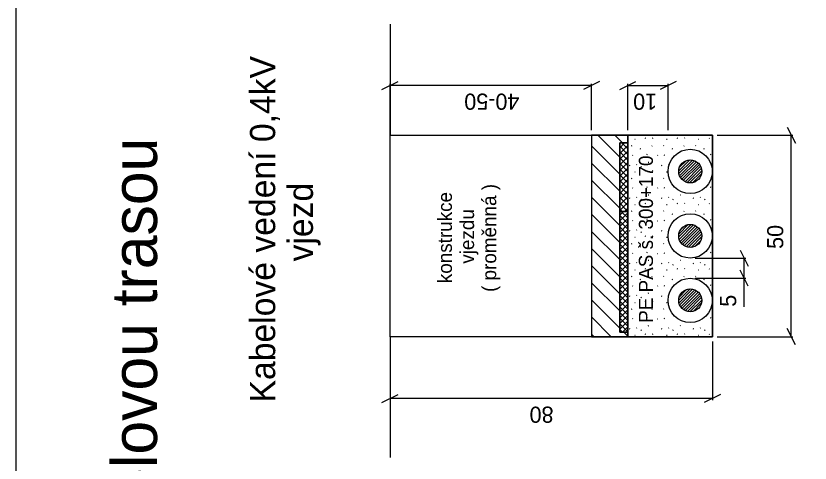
# Model space of a CAD drawing. Extents: x -762592 to -762444, y -1032635 to -1032425.
# Drawn here: x -762592.03 to -762560.49, y -1032598.54 to -1032580.78 of the extents above; entities that cross this region are included whole.
import ezdxf

# ---------------------------------------------------------------- set-up
doc = ezdxf.new("R2010")
doc.units = 0
for name, color, linetype in [('Chráničky - koruflex', 7, 'Continuous'), ('Implicitní', 7, 'Continuous'), ('Kabeláž - kabelové vedení HDV - stávající', 7, 'Continuous'), ('Tisk', 7, 'Continuous'), ('X ŘEZY TRASOU', 7, 'Continuous'), ('X ŘEZY TRASOU - KÓTY', 7, 'Continuous'), ('X ŘEZY TRASOU - ŠRAFY', 7, 'Continuous')]:
    doc.layers.add(name, color=color, linetype=linetype)

msp = doc.modelspace()

# ---------------------------------------------------------------- linework, layer by layer
at = {"layer": 'Kabeláž - kabelové vedení HDV - stávající'}
for p, q in [((-762565.703, -1032586.936), (-762565.271, -1032586.504)), ((-762565.696, -1032587.042), (-762565.164, -1032586.51)), ((-762565.674, -1032586.794), (-762565.414, -1032586.534)), ((-762565.67, -1032587.13), (-762565.077, -1032586.537)), ((-762565.632, -1032587.204), (-762565.002, -1032586.575)), ((-762565.582, -1032587.268), (-762564.939, -1032586.625)), ((-762565.523, -1032587.322), (-762564.885, -1032586.684)), ((-762565.453, -1032587.365), (-762564.842, -1032586.754)), ((-762565.371, -1032587.397), (-762564.81, -1032586.836)), ((-762565.275, -1032587.413), (-762564.793, -1032586.932)), ((-762565.152, -1032587.403), (-762564.803, -1032587.054)), ((-762565.702, -1032589.559), (-762565.207, -1032589.065)), ((-762565.697, -1032589.442), (-762565.325, -1032589.07)), ((-762565.683, -1032589.654), (-762565.113, -1032589.084)), ((-762565.65, -1032589.734), (-762565.033, -1032589.117)), ((-762565.614, -1032589.245), (-762565.524, -1032589.155)), ((-762565.605, -1032589.802), (-762564.965, -1032589.162)), ((-762565.55, -1032589.86), (-762564.907, -1032589.217)), ((-762565.484, -1032589.908), (-762564.859, -1032589.283)), ((-762565.409, -1032589.945), (-762564.822, -1032589.359)), ((-762565.318, -1032589.968), (-762564.799, -1032589.448)), ((-762565.209, -1032589.972), (-762564.795, -1032589.557)), ((-762565.055, -1032589.931), (-762564.837, -1032589.713)), ((-762565.704, -1032592.07), (-762565.257, -1032591.623)), ((-762565.694, -1032592.173), (-762565.153, -1032591.633)), ((-762565.68, -1032591.933), (-762565.394, -1032591.647)), ((-762565.667, -1032592.259), (-762565.068, -1032591.661)), ((-762565.626, -1032592.332), (-762564.994, -1032591.7)), ((-762565.576, -1032592.395), (-762564.932, -1032591.751)), ((-762565.516, -1032592.448), (-762564.88, -1032591.812)), ((-762565.444, -1032592.489), (-762564.837, -1032591.882)), ((-762565.361, -1032592.52), (-762564.808, -1032591.966)), ((-762565.262, -1032592.533), (-762564.794, -1032592.065)), ((-762565.134, -1032592.519), (-762564.808, -1032592.193))]:
    msp.add_line(p, q, dxfattribs=at)
at = {"layer": 'Tisk'}
msp.add_lwpolyline([(-762589.528, -1032529.685), (-762592.028, -1032529.685), (-762592.028, -1032634.685), (-762443.528, -1032634.685), (-762443.528, -1032529.685), (-762446.028, -1032529.685)], dxfattribs=at)
at = {"layer": 'X ŘEZY TRASOU'}
for p, q in [((-762577.169, -1032581.118), (-762577.169, -1032585.518)), ((-762577.169, -1032593.518), (-762577.169, -1032585.518)), ((-762577.169, -1032585.518), (-762567.729, -1032585.518)), ((-762569.169, -1032585.518), (-762569.169, -1032593.518)), ((-762567.729, -1032585.518), (-762567.729, -1032593.518)), ((-762567.729, -1032593.518), (-762567.729, -1032585.518)), ((-762567.729, -1032585.518), (-762564.369, -1032585.518)), ((-762564.369, -1032585.518), (-762564.369, -1032593.518)), ((-762568.049, -1032586.019), (-762567.853, -1032585.823)), ((-762567.729, -1032585.823), (-762568.049, -1032585.823)), ((-762568.049, -1032585.823), (-762568.049, -1032588.543)), ((-762567.729, -1032585.823), (-762568.049, -1032585.823)), ((-762568.049, -1032585.823), (-762568.049, -1032588.543)), ((-762568.049, -1032586.245), (-762567.729, -1032585.925)), ((-762567.729, -1032586.281), (-762568.049, -1032585.961)), ((-762567.729, -1032586.055), (-762567.96, -1032585.823)), ((-762567.729, -1032585.828), (-762567.734, -1032585.823)), ((-762567.729, -1032588.543), (-762567.729, -1032585.823)), ((-762567.729, -1032588.543), (-762567.729, -1032585.823)), ((-762568.049, -1032586.471), (-762567.729, -1032586.151)), ((-762567.729, -1032586.507), (-762568.049, -1032586.187)), ((-762568.049, -1032586.697), (-762567.729, -1032586.377)), ((-762567.729, -1032586.733), (-762568.049, -1032586.413)), ((-762568.049, -1032586.924), (-762567.729, -1032586.604)), ((-762567.729, -1032586.96), (-762568.049, -1032586.64)), ((-762568.049, -1032587.15), (-762567.729, -1032586.83)), ((-762567.729, -1032587.186), (-762568.049, -1032586.866)), ((-762568.049, -1032587.376), (-762567.729, -1032587.056)), ((-762567.729, -1032587.412), (-762568.049, -1032587.092)), ((-762568.049, -1032587.603), (-762567.729, -1032587.283)), ((-762567.729, -1032587.638), (-762568.049, -1032587.318)), ((-762568.049, -1032587.829), (-762567.729, -1032587.509)), ((-762567.729, -1032587.865), (-762568.049, -1032587.545)), ((-762568.049, -1032588.055), (-762567.729, -1032587.735)), ((-762567.729, -1032588.091), (-762568.049, -1032587.771)), ((-762568.049, -1032588.281), (-762567.729, -1032587.961)), ((-762567.729, -1032588.317), (-762568.049, -1032587.997)), ((-762568.049, -1032588.508), (-762567.729, -1032588.188)), ((-762567.729, -1032588.543), (-762568.049, -1032588.224)), ((-762567.955, -1032588.543), (-762568.049, -1032588.45)), ((-762568.049, -1032588.697), (-762567.895, -1032588.543)), ((-762568.049, -1032588.543), (-762567.729, -1032588.543)), ((-762568.049, -1032588.543), (-762567.729, -1032588.543)), ((-762568.049, -1032593.343), (-762568.049, -1032588.543)), ((-762568.049, -1032588.543), (-762567.729, -1032588.543)), ((-762567.729, -1032588.543), (-762568.049, -1032588.543)), ((-762568.049, -1032588.543), (-762568.049, -1032593.343)), ((-762567.729, -1032588.804), (-762567.989, -1032588.543)), ((-762567.858, -1032588.543), (-762567.729, -1032588.414)), ((-762567.729, -1032588.578), (-762567.763, -1032588.543)), ((-762567.729, -1032588.543), (-762567.729, -1032593.343)), ((-762567.729, -1032593.343), (-762567.729, -1032588.543)), ((-762568.049, -1032588.923), (-762567.729, -1032588.603)), ((-762567.729, -1032589.03), (-762568.049, -1032588.71)), ((-762568.049, -1032589.149), (-762567.729, -1032588.829)), ((-762567.729, -1032589.256), (-762568.049, -1032588.936)), ((-762568.049, -1032589.376), (-762567.729, -1032589.056)), ((-762567.729, -1032589.483), (-762568.049, -1032589.163)), ((-762568.049, -1032589.602), (-762567.729, -1032589.282)), ((-762567.729, -1032589.709), (-762568.049, -1032589.389)), ((-762568.049, -1032589.828), (-762567.729, -1032589.508)), ((-762567.729, -1032589.935), (-762568.049, -1032589.615)), ((-762568.049, -1032590.054), (-762567.729, -1032589.734)), ((-762567.729, -1032590.162), (-762568.049, -1032589.842)), ((-762568.049, -1032590.281), (-762567.729, -1032589.961)), ((-762567.729, -1032590.388), (-762568.049, -1032590.068)), ((-762568.049, -1032590.507), (-762567.729, -1032590.187)), ((-762567.729, -1032590.614), (-762568.049, -1032590.294)), ((-762568.049, -1032590.733), (-762567.729, -1032590.413)), ((-762567.729, -1032590.84), (-762568.049, -1032590.52)), ((-762568.049, -1032590.959), (-762567.729, -1032590.639)), ((-762567.729, -1032591.067), (-762568.049, -1032590.747)), ((-762568.049, -1032591.186), (-762567.729, -1032590.866)), ((-762567.729, -1032591.293), (-762568.049, -1032590.973)), ((-762568.049, -1032591.412), (-762567.729, -1032591.092)), ((-762567.729, -1032591.519), (-762568.049, -1032591.199)), ((-762568.049, -1032591.638), (-762567.729, -1032591.318)), ((-762567.729, -1032591.745), (-762568.049, -1032591.425)), ((-762568.049, -1032591.865), (-762567.729, -1032591.545)), ((-762567.729, -1032591.972), (-762568.049, -1032591.652)), ((-762568.049, -1032592.091), (-762567.729, -1032591.771)), ((-762567.729, -1032592.198), (-762568.049, -1032591.878)), ((-762568.049, -1032592.317), (-762567.729, -1032591.997)), ((-762567.729, -1032592.424), (-762568.049, -1032592.104)), ((-762568.049, -1032592.543), (-762567.729, -1032592.223)), ((-762567.729, -1032592.651), (-762568.049, -1032592.331)), ((-762568.049, -1032592.77), (-762567.729, -1032592.45)), ((-762567.729, -1032592.877), (-762568.049, -1032592.557)), ((-762568.049, -1032592.996), (-762567.729, -1032592.676)), ((-762567.729, -1032593.103), (-762568.049, -1032592.783)), ((-762568.049, -1032593.222), (-762567.729, -1032592.902)), ((-762567.729, -1032593.329), (-762568.049, -1032593.009)), ((-762567.941, -1032593.343), (-762568.049, -1032593.236)), ((-762567.944, -1032593.343), (-762567.729, -1032593.128)), ((-762577.169, -1032593.518), (-762577.169, -1032598.318)), ((-762567.729, -1032593.518), (-762577.169, -1032593.518)), ((-762567.729, -1032593.343), (-762568.049, -1032593.343)), ((-762568.049, -1032593.343), (-762567.729, -1032593.343)), ((-762564.369, -1032593.518), (-762567.729, -1032593.518)), ((-762577.169, -1032595.118), (-762577.169, -1032597.413))]:
    msp.add_line(p, q, dxfattribs=at)
for centre, radius in [((-762565.249, -1032586.958), 0.88), ((-762565.249, -1032586.958), 0.456), ((-762565.249, -1032589.518), 0.88), ((-762565.249, -1032589.518), 0.456), ((-762565.249, -1032592.078), 0.88), ((-762565.249, -1032592.078), 0.456)]:
    msp.add_circle(centre, radius, dxfattribs=at)
at = {"layer": 'X ŘEZY TRASOU - KÓTY'}
for p, q in [((-762577.489, -1032583.709), (-762576.849, -1032583.389)), ((-762577.169, -1032585.518), (-762577.169, -1032583.485)), ((-762568.849, -1032583.389), (-762569.489, -1032583.709)), ((-762569.169, -1032585.326), (-762569.169, -1032583.485)), ((-762568.049, -1032583.709), (-762567.409, -1032583.389)), ((-762567.729, -1032585.326), (-762567.729, -1032583.485)), ((-762565.809, -1032583.389), (-762566.449, -1032583.709)), ((-762566.129, -1032585.326), (-762566.129, -1032583.485)), ((-762569.169, -1032583.549), (-762577.169, -1032583.549)), ((-762567.729, -1032583.549), (-762566.129, -1032583.549)), ((-762561.394, -1032585.198), (-762561.074, -1032585.838)), ((-762564.177, -1032585.518), (-762561.17, -1032585.518)), ((-762561.234, -1032593.518), (-762561.234, -1032585.518)), ((-762563.264, -1032590.078), (-762562.944, -1032590.718)), ((-762565.057, -1032590.398), (-762563.04, -1032590.398)), ((-762563.104, -1032591.198), (-762563.104, -1032590.398)), ((-762562.944, -1032591.518), (-762563.264, -1032590.878)), ((-762565.057, -1032591.198), (-762563.04, -1032591.198)), ((-762563.104, -1032592.331), (-762563.104, -1032591.198)), ((-762561.074, -1032593.838), (-762561.394, -1032593.198)), ((-762564.177, -1032593.518), (-762561.17, -1032593.518)), ((-762577.169, -1032593.71), (-762577.169, -1032596.039)), ((-762564.369, -1032593.71), (-762564.369, -1032596.039)), ((-762577.489, -1032596.135), (-762576.849, -1032595.815)), ((-762564.369, -1032595.975), (-762577.169, -1032595.975)), ((-762564.049, -1032595.815), (-762564.689, -1032596.135))]:
    msp.add_line(p, q, dxfattribs=at)
at = {"layer": 'X ŘEZY TRASOU - ŠRAFY'}
for p, q in [((-762569.169, -1032585.518), (-762569.169, -1032593.518)), ((-762567.729, -1032585.518), (-762569.169, -1032585.518)), ((-762568.049, -1032586.387), (-762568.917, -1032585.518)), ((-762567.933, -1032585.823), (-762568.238, -1032585.518)), ((-762567.729, -1032585.823), (-762567.729, -1032585.518)), ((-762564.369, -1032585.518), (-762567.729, -1032585.518)), ((-762567.729, -1032585.518), (-762567.729, -1032585.823)), ((-762567.454, -1032585.677), (-762567.43, -1032585.674)), ((-762567.007, -1032585.652), (-762567.032, -1032585.641)), ((-762566.743, -1032585.635), (-762566.726, -1032585.624)), ((-762566.19, -1032585.677), (-762566.165, -1032585.674)), ((-762565.743, -1032585.652), (-762565.767, -1032585.641)), ((-762565.478, -1032585.635), (-762565.462, -1032585.624)), ((-762564.925, -1032585.677), (-762564.901, -1032585.674)), ((-762564.478, -1032585.652), (-762564.503, -1032585.641)), ((-762564.369, -1032586.958), (-762564.369, -1032585.518)), ((-762568.049, -1032587.065), (-762569.169, -1032585.945)), ((-762568.049, -1032588.543), (-762568.049, -1032585.823)), ((-762568.049, -1032585.823), (-762567.729, -1032585.823)), ((-762567.729, -1032585.823), (-762567.729, -1032588.543)), ((-762567.575, -1032585.945), (-762567.558, -1032585.934)), ((-762566.772, -1032585.955), (-762566.756, -1032585.944)), ((-762566.31, -1032585.945), (-762566.294, -1032585.934)), ((-762565.507, -1032585.955), (-762565.491, -1032585.944)), ((-762565.046, -1032585.945), (-762565.029, -1032585.934)), ((-762567.522, -1032586.321), (-762567.547, -1032586.31)), ((-762567.208, -1032586.074), (-762567.233, -1032586.063)), ((-762566.945, -1032586.294), (-762566.969, -1032586.283)), ((-762566.55, -1032586.329), (-762566.534, -1032586.319)), ((-762566.258, -1032586.321), (-762566.282, -1032586.31)), ((-762565.944, -1032586.074), (-762565.968, -1032586.063)), ((-762564.679, -1032586.074), (-762564.703, -1032586.063)), ((-762564.416, -1032586.294), (-762564.44, -1032586.283)), ((-762568.049, -1032587.744), (-762569.169, -1032586.624)), ((-762566.913, -1032586.596), (-762566.897, -1032586.586)), ((-762564.384, -1032586.596), (-762564.369, -1032586.586)), ((-762564.369, -1032586.586), (-762564.368, -1032586.586)), ((-762567.633, -1032586.732), (-762567.657, -1032586.721)), ((-762567.454, -1032586.974), (-762567.43, -1032586.971)), ((-762567.382, -1032586.693), (-762567.366, -1032586.682)), ((-762567.208, -1032586.789), (-762567.192, -1032586.778)), ((-762567.202, -1032586.778), (-762567.186, -1032586.767)), ((-762567.007, -1032586.949), (-762567.032, -1032586.938)), ((-762566.743, -1032586.932), (-762566.726, -1032586.921)), ((-762566.369, -1032586.732), (-762566.393, -1032586.721)), ((-762566.19, -1032586.974), (-762566.165, -1032586.971)), ((-762566.118, -1032586.693), (-762566.102, -1032586.682)), ((-762564.369, -1032589.518), (-762564.369, -1032586.958)), ((-762567.575, -1032587.242), (-762567.558, -1032587.231)), ((-762566.772, -1032587.252), (-762566.756, -1032587.241)), ((-762566.31, -1032587.242), (-762566.294, -1032587.231)), ((-762568.049, -1032588.423), (-762569.169, -1032587.303)), ((-762567.208, -1032587.371), (-762567.233, -1032587.36)), ((-762566.945, -1032587.59), (-762566.969, -1032587.58)), ((-762564.416, -1032587.59), (-762564.44, -1032587.58)), ((-762567.522, -1032587.618), (-762567.547, -1032587.607)), ((-762566.913, -1032587.893), (-762566.897, -1032587.883)), ((-762566.55, -1032587.626), (-762566.534, -1032587.616)), ((-762566.258, -1032587.618), (-762566.282, -1032587.607)), ((-762565.649, -1032587.893), (-762565.633, -1032587.883)), ((-762564.384, -1032587.893), (-762564.369, -1032587.883)), ((-762564.369, -1032587.883), (-762564.368, -1032587.883)), ((-762568.049, -1032589.102), (-762569.169, -1032587.982)), ((-762567.633, -1032588.029), (-762567.657, -1032588.018)), ((-762567.382, -1032587.99), (-762567.366, -1032587.979)), ((-762567.208, -1032588.086), (-762567.192, -1032588.075)), ((-762567.202, -1032588.075), (-762567.186, -1032588.064)), ((-762566.743, -1032588.229), (-762566.726, -1032588.218)), ((-762566.369, -1032588.029), (-762566.393, -1032588.018)), ((-762566.118, -1032587.99), (-762566.102, -1032587.979)), ((-762565.943, -1032588.086), (-762565.927, -1032588.075)), ((-762565.937, -1032588.075), (-762565.921, -1032588.064)), ((-762565.478, -1032588.229), (-762565.462, -1032588.218)), ((-762565.104, -1032588.029), (-762565.128, -1032588.018)), ((-762564.853, -1032587.99), (-762564.837, -1032587.979)), ((-762564.679, -1032588.086), (-762564.663, -1032588.075)), ((-762564.673, -1032588.075), (-762564.656, -1032588.064)), ((-762568.049, -1032593.343), (-762568.049, -1032588.543)), ((-762567.729, -1032588.543), (-762567.729, -1032593.343)), ((-762567.575, -1032588.539), (-762567.558, -1032588.528)), ((-762567.454, -1032588.271), (-762567.43, -1032588.268)), ((-762567.007, -1032588.246), (-762567.032, -1032588.235)), ((-762566.772, -1032588.549), (-762566.756, -1032588.538)), ((-762566.31, -1032588.539), (-762566.294, -1032588.528)), ((-762566.19, -1032588.271), (-762566.165, -1032588.268)), ((-762565.743, -1032588.246), (-762565.767, -1032588.235)), ((-762565.507, -1032588.549), (-762565.491, -1032588.538)), ((-762565.046, -1032588.539), (-762565.029, -1032588.528)), ((-762564.925, -1032588.271), (-762564.901, -1032588.268)), ((-762564.478, -1032588.246), (-762564.503, -1032588.235)), ((-762568.049, -1032589.781), (-762569.169, -1032588.661)), ((-762567.208, -1032588.668), (-762567.233, -1032588.657)), ((-762565.944, -1032588.668), (-762565.968, -1032588.657)), ((-762564.679, -1032588.668), (-762564.703, -1032588.657)), ((-762567.522, -1032588.914), (-762567.547, -1032588.904)), ((-762566.945, -1032588.887), (-762566.969, -1032588.877)), ((-762566.913, -1032589.19), (-762566.897, -1032589.18)), ((-762566.55, -1032588.923), (-762566.534, -1032588.913)), ((-762566.258, -1032588.914), (-762566.282, -1032588.904)), ((-762564.416, -1032588.887), (-762564.44, -1032588.877)), ((-762564.384, -1032589.19), (-762564.369, -1032589.18)), ((-762564.369, -1032589.18), (-762564.368, -1032589.18)), ((-762568.049, -1032590.459), (-762569.169, -1032589.339)), ((-762567.633, -1032589.326), (-762567.657, -1032589.315)), ((-762567.382, -1032589.287), (-762567.366, -1032589.276)), ((-762567.208, -1032589.383), (-762567.192, -1032589.372)), ((-762567.202, -1032589.372), (-762567.186, -1032589.361)), ((-762566.369, -1032589.326), (-762566.393, -1032589.315)), ((-762566.118, -1032589.287), (-762566.102, -1032589.276)), ((-762567.454, -1032589.568), (-762567.43, -1032589.565)), ((-762567.007, -1032589.543), (-762567.032, -1032589.532)), ((-762566.743, -1032589.526), (-762566.726, -1032589.515)), ((-762566.19, -1032589.568), (-762566.165, -1032589.565)), ((-762564.369, -1032592.078), (-762564.369, -1032589.518)), ((-762568.049, -1032591.138), (-762569.169, -1032590.018)), ((-762567.575, -1032589.836), (-762567.558, -1032589.825)), ((-762567.208, -1032589.965), (-762567.233, -1032589.954)), ((-762566.772, -1032589.846), (-762566.756, -1032589.835)), ((-762566.31, -1032589.836), (-762566.294, -1032589.825)), ((-762567.522, -1032590.211), (-762567.547, -1032590.201)), ((-762566.945, -1032590.184), (-762566.969, -1032590.174)), ((-762566.55, -1032590.22), (-762566.534, -1032590.21)), ((-762566.258, -1032590.211), (-762566.282, -1032590.201)), ((-762564.416, -1032590.184), (-762564.44, -1032590.174)), ((-762568.049, -1032591.817), (-762569.169, -1032590.697)), ((-762567.633, -1032590.623), (-762567.657, -1032590.612)), ((-762567.382, -1032590.583), (-762567.366, -1032590.573)), ((-762567.208, -1032590.68), (-762567.192, -1032590.669)), ((-762567.202, -1032590.669), (-762567.186, -1032590.658)), ((-762566.913, -1032590.487), (-762566.897, -1032590.477)), ((-762566.369, -1032590.623), (-762566.393, -1032590.612)), ((-762566.118, -1032590.583), (-762566.102, -1032590.573)), ((-762565.943, -1032590.68), (-762565.927, -1032590.669)), ((-762565.937, -1032590.669), (-762565.921, -1032590.658)), ((-762565.649, -1032590.487), (-762565.633, -1032590.477)), ((-762565.104, -1032590.623), (-762565.128, -1032590.612)), ((-762564.853, -1032590.583), (-762564.837, -1032590.573)), ((-762564.679, -1032590.68), (-762564.663, -1032590.669)), ((-762564.673, -1032590.669), (-762564.656, -1032590.658)), ((-762564.384, -1032590.487), (-762564.369, -1032590.477)), ((-762564.369, -1032590.477), (-762564.368, -1032590.477)), ((-762567.454, -1032590.865), (-762567.43, -1032590.862)), ((-762567.007, -1032590.84), (-762567.032, -1032590.829)), ((-762566.743, -1032590.823), (-762566.726, -1032590.812)), ((-762566.19, -1032590.865), (-762566.165, -1032590.862)), ((-762565.743, -1032590.84), (-762565.767, -1032590.829)), ((-762565.478, -1032590.823), (-762565.462, -1032590.812)), ((-762564.925, -1032590.865), (-762564.901, -1032590.862)), ((-762564.478, -1032590.84), (-762564.503, -1032590.829)), ((-762568.049, -1032592.496), (-762569.169, -1032591.376)), ((-762567.575, -1032591.133), (-762567.558, -1032591.122)), ((-762567.208, -1032591.262), (-762567.233, -1032591.251)), ((-762566.772, -1032591.143), (-762566.756, -1032591.132)), ((-762566.31, -1032591.133), (-762566.294, -1032591.122)), ((-762565.944, -1032591.262), (-762565.968, -1032591.251)), ((-762565.507, -1032591.143), (-762565.491, -1032591.132)), ((-762565.046, -1032591.133), (-762565.029, -1032591.122)), ((-762564.679, -1032591.262), (-762564.703, -1032591.251)), ((-762567.522, -1032591.508), (-762567.547, -1032591.498)), ((-762566.945, -1032591.481), (-762566.969, -1032591.471)), ((-762566.55, -1032591.517), (-762566.534, -1032591.506)), ((-762566.258, -1032591.508), (-762566.282, -1032591.498)), ((-762564.416, -1032591.481), (-762564.44, -1032591.471)), ((-762567.633, -1032591.92), (-762567.657, -1032591.909)), ((-762567.382, -1032591.88), (-762567.366, -1032591.87)), ((-762567.208, -1032591.977), (-762567.192, -1032591.966)), ((-762567.202, -1032591.966), (-762567.186, -1032591.955)), ((-762566.913, -1032591.784), (-762566.897, -1032591.773)), ((-762566.369, -1032591.92), (-762566.393, -1032591.909)), ((-762566.118, -1032591.88), (-762566.102, -1032591.87)), ((-762564.384, -1032591.784), (-762564.369, -1032591.774)), ((-762564.369, -1032591.774), (-762564.368, -1032591.773)), ((-762568.049, -1032593.175), (-762569.169, -1032592.055)), ((-762567.454, -1032592.162), (-762567.43, -1032592.159)), ((-762567.007, -1032592.137), (-762567.032, -1032592.126)), ((-762566.743, -1032592.12), (-762566.726, -1032592.109)), ((-762566.19, -1032592.162), (-762566.165, -1032592.159)), ((-762564.369, -1032593.518), (-762564.369, -1032592.078)), ((-762567.575, -1032592.43), (-762567.558, -1032592.419)), ((-762567.208, -1032592.559), (-762567.233, -1032592.548)), ((-762566.772, -1032592.44), (-762566.756, -1032592.429)), ((-762566.31, -1032592.43), (-762566.294, -1032592.419)), ((-762568.384, -1032593.518), (-762569.169, -1032592.734)), ((-762567.522, -1032592.805), (-762567.547, -1032592.795)), ((-762566.945, -1032592.778), (-762566.969, -1032592.767)), ((-762566.55, -1032592.814), (-762566.534, -1032592.803)), ((-762566.258, -1032592.805), (-762566.282, -1032592.795)), ((-762564.416, -1032592.778), (-762564.44, -1032592.767)), ((-762567.633, -1032593.217), (-762567.657, -1032593.206)), ((-762567.382, -1032593.177), (-762567.366, -1032593.167)), ((-762567.208, -1032593.274), (-762567.192, -1032593.263)), ((-762567.202, -1032593.263), (-762567.186, -1032593.252)), ((-762566.913, -1032593.081), (-762566.897, -1032593.07)), ((-762566.369, -1032593.217), (-762566.393, -1032593.206)), ((-762566.118, -1032593.177), (-762566.102, -1032593.167)), ((-762565.943, -1032593.274), (-762565.927, -1032593.263)), ((-762565.937, -1032593.263), (-762565.921, -1032593.252)), ((-762565.649, -1032593.081), (-762565.633, -1032593.07)), ((-762565.104, -1032593.217), (-762565.128, -1032593.206)), ((-762564.853, -1032593.177), (-762564.837, -1032593.167)), ((-762564.679, -1032593.274), (-762564.663, -1032593.263)), ((-762564.673, -1032593.263), (-762564.656, -1032593.252)), ((-762564.384, -1032593.081), (-762564.369, -1032593.071)), ((-762564.369, -1032593.071), (-762564.368, -1032593.07)), ((-762569.063, -1032593.518), (-762569.169, -1032593.412)), ((-762569.169, -1032593.518), (-762567.729, -1032593.518)), ((-762567.729, -1032593.343), (-762568.049, -1032593.343)), ((-762567.729, -1032593.495), (-762567.88, -1032593.343)), ((-762567.729, -1032593.518), (-762567.729, -1032593.343)), ((-762567.729, -1032593.343), (-762567.729, -1032593.518)), ((-762567.729, -1032593.518), (-762564.369, -1032593.518)), ((-762567.454, -1032593.459), (-762567.43, -1032593.456)), ((-762567.007, -1032593.434), (-762567.032, -1032593.423)), ((-762566.743, -1032593.417), (-762566.726, -1032593.406)), ((-762566.19, -1032593.459), (-762566.165, -1032593.456)), ((-762565.743, -1032593.434), (-762565.767, -1032593.423)), ((-762565.478, -1032593.417), (-762565.462, -1032593.406)), ((-762564.925, -1032593.459), (-762564.901, -1032593.456)), ((-762564.478, -1032593.434), (-762564.503, -1032593.423))]:
    msp.add_line(p, q, dxfattribs=at)
for centre in [(-762565.249, -1032586.958), (-762565.249, -1032589.518)]:
    msp.add_circle(centre, 0.88, dxfattribs=at)
msp.add_arc((-762565.249, -1032592.078), 0.88, 0.0067, 359.9933, dxfattribs=at)

# ---------------------------------------------------------------- texts
at = {"layer": 'Chráničky - koruflex'}
for s, p in [('Kabelové vedení 0,4kV', (-762581.731, -1032596.129)), ('vjezd', (-762580.231, -1032590.532))]:
    msp.add_text(s, height=1, rotation=90, dxfattribs=at).set_placement(p)
at = {"layer": 'Implicitní'}
msp.add_text('Řezy kabelovou trasou', height=1.8, rotation=90, dxfattribs=at).set_placement((-762586.423, -1032610.105))
at = {"layer": 'X ŘEZY TRASOU'}
for s, p in [('PE PAS š. 300+170', (-762566.729, -1032592.968)), ('( proměnná )', (-762572.953, -1032591.743)), ('konstrukce', (-762574.713, -1032591.394)), ('vjezdu', (-762573.833, -1032590.621))]:
    msp.add_text(s, height=0.56, rotation=90, dxfattribs=at).set_placement(p)
at = {"layer": 'X ŘEZY TRASOU - KÓTY'}
for s, rotation, p in [('40-50', 180, (-762572.033, -1032583.869)), ('10', 180, (-762566.563, -1032583.869)), ('50', 90, (-762561.554, -1032590.034)), ('5', 90, (-762563.424, -1032592.331)), ('80', 180, (-762570.677, -1032596.295))]:
    msp.add_text(s, height=0.64, rotation=rotation, dxfattribs=at).set_placement(p)

doc.saveas('drawing.dxf')
